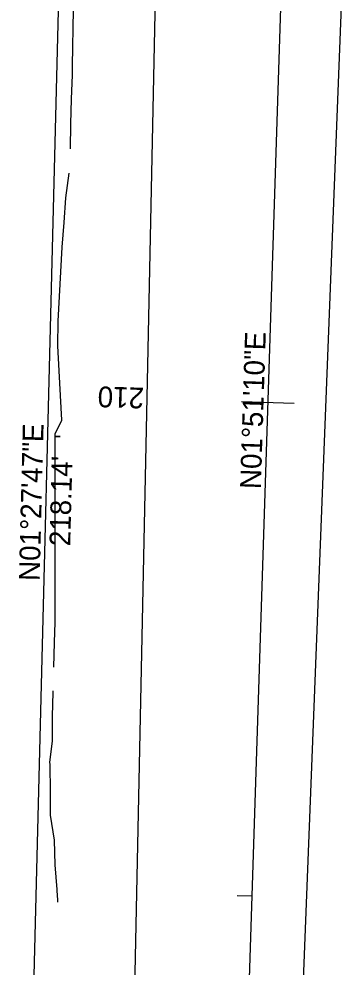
# Model space of a CAD drawing. Extents: x 1145508 to 2262867, y -3126236 to 2021677.
# Drawn here: x 1151647 to 1151712.6, y 2019962.8 to 2020154.7 of the extents above; entities that cross this region are included whole.
import ezdxf

# ---------------------------------------------------------------- set-up
doc = ezdxf.new("R2010")
doc.units = 0
for name, color, linetype in [('DSN_RDWY_Alignment Annotation', 7, 'Continuous'), ('DSN_RDWY_Const Limits', 7, 'Continuous'), ('DSN_ROW_Annotation', 7, 'Continuous'), ('DSN_ROW_Esmnt', 7, 'Continuous'), ('E_Const Align', 7, 'Continuous'), ('EX_ROW', 7, 'Continuous'), ('EX_SECTION', 7, 'Continuous')]:
    doc.layers.add(name, color=color, linetype=linetype)

msp = doc.modelspace()

# ---------------------------------------------------------------- linework, layer by layer
at = {"layer": 'DSN_RDWY_Alignment Annotation'}
for p, q in [((1151692.1, 2020077.26), (1151702.72, 2020076.92)), ((1151691.21, 2019977.24), (1151694.21, 2019977.14))]:
    msp.add_line(p, q, dxfattribs=at)
at = {"layer": 'DSN_RDWY_Const Limits'}
for points in [[(1151657.45, 2020128.41), (1151657.53, 2020133.41), (1151657.67, 2020138.41), (1151657.86, 2020143.39), (1151657.86, 2020143.4), (1151657.89, 2020145.8), (1151657.92, 2020148.41), (1151658.01, 2020153.41), (1151658.13, 2020158.4)], [(1151654.07, 2020023.46), (1151654.22, 2020028.46), (1151654.35, 2020032.56), (1151654.38, 2020033.46), (1151654.38, 2020033.62), (1151654.38, 2020033.72), (1151654.33, 2020038.46), (1151654.34, 2020043.47), (1151654.34, 2020048.47), (1151654.35, 2020051.56), (1151654.35, 2020051.88), (1151654.35, 2020053.47), (1151654.33, 2020058.47), (1151654.35, 2020063.48), (1151654.36, 2020068.48), (1151654.37, 2020070.13), (1151655.34, 2020070.17), (1151654.37, 2020070.21), (1151654.37, 2020070.56), (1151654.37, 2020070.71), (1151655.71, 2020073.44), (1151655.43, 2020078.45), (1151655.17, 2020083.46), (1151654.91, 2020088.47), (1151654.96, 2020093.47), (1151655.23, 2020098.47), (1151655.5, 2020103.46), (1151655.77, 2020108.45), (1151656.18, 2020113.44), (1151656.51, 2020118.44), (1151657.21, 2020123.42)], [(1151654.91, 2019975.89), (1151654.88, 2019976.55), (1151654.85, 2019977.01), (1151654.74, 2019978.42), (1151654.36, 2019983.43), (1151654.2, 2019988.44), (1151653.43, 2019993.47), (1151653.39, 2019993.76), (1151653.39, 2019994.11), (1151653.42, 2019994.47), (1151653.37, 2019998.47), (1151653.31, 2020003.48), (1151653.31, 2020003.72), (1151653.3, 2020004.22), (1151653.83, 2020008.46), (1151653.79, 2020013.47), (1151653.95, 2020018.39), (1151653.95, 2020018.47), (1151653.96, 2020018.67)]]:
    msp.add_lwpolyline(points, dxfattribs=at)
at = {"layer": 'DSN_ROW_Esmnt'}
msp.add_line((1151649.76, 2019948.86), (1151655.32, 2020166.93), dxfattribs=at)
at = {"layer": 'E_Const Align'}
msp.add_line((1151693.25, 2019947.42), (1151701.6, 2020205.53), dxfattribs=at)
at = {"layer": 'EX_ROW'}
msp.add_line((1151666.04, 2019745.81), (1151674.8, 2020166.2), dxfattribs=at)
at = {"layer": 'EX_SECTION'}
msp.add_line((1151660.65, 2018840.69), (1151712.63, 2020164.79), dxfattribs=at)

# ---------------------------------------------------------------- texts
at = {"layer": 'DSN_RDWY_Alignment Annotation'}
for s, rotation, p in [('N01°51\'10"E', 88.1473, (1151695.97, 2020059.46)), ('210', 178.1473, (1151672.4, 2020080))]:
    msp.add_text(s, height=4.2, rotation=rotation, dxfattribs=at).set_placement(p)
at = {"layer": 'DSN_ROW_Annotation'}
for s, p in [('N01°27\'47"E', (1151651.2, 2020040.87)), ("218.14'", (1151657.39, 2020047.91))]:
    msp.add_text(s, height=4.2, rotation=88.537, dxfattribs=at).set_placement(p)

doc.saveas('drawing.dxf')
